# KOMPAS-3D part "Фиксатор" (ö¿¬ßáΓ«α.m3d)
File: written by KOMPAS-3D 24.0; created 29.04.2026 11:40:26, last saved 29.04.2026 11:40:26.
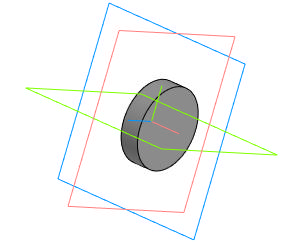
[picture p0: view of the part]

Document properties: Автор: USG_411; Полное имя файла: C:\Users\USG_411\Desktop\ИА-2904_411-12\Фиксатор.m3d

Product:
- Part/product: Фиксатор
    Масса: 0.022657

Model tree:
1. Эскиз:1
2. Элемент выдавливания:1
     Расстояние 1 = 6
3. Эскиз:2  (with: Грань.Элемент выдавливания:1)
4. Элемент выдавливания:2
     Расстояние 1 = 6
